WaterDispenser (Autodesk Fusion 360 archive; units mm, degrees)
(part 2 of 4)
sketch "Sketch2" plane through (206.7, 0, 0) normal (1, 0, 0) x axis (0, 0, -1)
  line L1 (-6.7, 180) -> (-1, 180)
  line L2 (-6.7, 170) -> (-6.7, 180)
  line L3 (-1, 170) -> (-6.7, 170)
  line L4 (-1, 160) -> (-1, 170)
  line L5 (-6.7, 160) -> (-1, 160)
  line L6 (-6.7, 150) -> (-6.7, 160)
  line L7 (-1, 150) -> (-6.7, 150)
  line L8 (-1, 140) -> (-1, 150)
  line L9 (-6.7, 140) -> (-1, 140)
  line L10 (-6.7, 130) -> (-6.7, 140)
  line L11 (-1, 130) -> (-6.7, 130)
  line L12 (-1, 120) -> (-1, 130)
  line L13 (-6.7, 120) -> (-1, 120)
  line L14 (-6.7, 110) -> (-6.7, 120)
  line L15 (-1, 110) -> (-6.7, 110)
  line L16 (-1, 100) -> (-1, 110)
  line L17 (-6.7, 100) -> (-1, 100)
  line L18 (-6.7, 90) -> (-6.7, 100)
  line L19 (-1, 90) -> (-6.7, 90)
  line L20 (-1, 80) -> (-1, 90)
  line L21 (-6.7, 80) -> (-1, 80)
  line L22 (-6.7, 70) -> (-6.7, 80)
  line L23 (-1, 70) -> (-6.7, 70)
  line L24 (-1, 60) -> (-1, 70)
  line L25 (-6.7, 60) -> (-1, 60)
  line L26 (-6.7, 50) -> (-6.7, 60)
  line L27 (-1, 50) -> (-6.7, 50)
  line L28 (-1, 40) -> (-1, 50)
  line L29 (-6.7, 40) -> (-1, 40)
  line L30 (-6.7, 30) -> (-6.7, 40)
  line L31 (-1, 30) -> (-6.7, 30)
  line L32 (-1, 20) -> (-1, 30)
  line L33 (-6.7, 20) -> (-1, 20)
  line L34 (-6.7, 10) -> (-6.7, 20)
  line L35 (-1, 10) -> (-6.7, 10)
  line L36 (-1, -5.7) -> (-1, 10)
  line L37 (75, -5.7) -> (-1, -5.7)
  line L38 (75, 245) -> (75, -5.7)
  line L39 (-6.7, 245) -> (75, 245)
  line L40 (-6.7, 230) -> (-6.7, 245)
  line L41 (-1, 230) -> (-6.7, 230)
  line L42 (-1, 220) -> (-1, 230)
  line L43 (-6.7, 220) -> (-1, 220)
  line L44 (-6.7, 210) -> (-6.7, 220)
  line L45 (-1, 210) -> (-6.7, 210)
  line L46 (-1, 200) -> (-1, 210)
  line L47 (-6.7, 200) -> (-1, 200)
  line L48 (-6.7, 190) -> (-6.7, 200)
  line L49 (-1, 190) -> (-6.7, 190)
  line L50 (-1, 180) -> (-1, 190)
  line L51 (-1, 245) -> (-1, 230)
  line L52 (9, 245) -> (-1, 245)
  line L53 (9, 239.3) -> (9, 245)
  line L54 (-1, 239.3) -> (9, 239.3)
  line L55 (-1, 245) -> (-1, 239.3)
  line L56 (9, 239.3) -> (19, 239.3)
  line L57 (9, 245) -> (9, 239.3)
  line L58 (19, 245) -> (9, 245)
  line L59 (19, 239.3) -> (19, 245)
  line L60 (19, 239.3) -> (29, 239.3)
  line L61 (19, 245) -> (19, 239.3)
  line L62 (29, 245) -> (19, 245)
  line L63 (29, 239.3) -> (29, 245)
  line L64 (29, 239.3) -> (39, 239.3)
  line L65 (29, 245) -> (29, 239.3)
  line L66 (39, 245) -> (29, 245)
  line L67 (39, 239.3) -> (39, 245)
  line L68 (39, 239.3) -> (49, 239.3)
  line L69 (39, 245) -> (39, 239.3)
  line L70 (49, 245) -> (39, 245)
  line L71 (49, 239.3) -> (49, 245)
  line L72 (49, 239.3) -> (59, 239.3)
  line L73 (49, 245) -> (49, 239.3)
  line L74 (59, 245) -> (49, 245)
  line L75 (59, 239.3) -> (59, 245)
  line L76 (59, 239.3) -> (69, 239.3)
  line L77 (59, 245) -> (59, 239.3)
  line L78 (69, 245) -> (59, 245)
  line L79 (69, 239.3) -> (69, 245)
  line L80 (75, 239.3) -> (69, 239.3)
  line L81 (75, 245) -> (69, 245)
  line L82 (75, 239.3) -> (75, 245)
  line L83 (9, -5.7) -> (-1, -5.7)
  line L84 (9, 0) -> (9, -5.7)
  line L85 (-1, 0) -> (9, 0)
  line L86 (-1, -5.7) -> (-1, 0)
  line L87 (19, 0) -> (19, -5.7)
  line L88 (9, 0) -> (19, 0)
  line L89 (9, -5.7) -> (9, 0)
  line L90 (19, -5.7) -> (9, -5.7)
  line L91 (29, 0) -> (29, -5.7)
  line L92 (19, 0) -> (29, 0)
  line L93 (19, -5.7) -> (19, 0)
  line L94 (29, -5.7) -> (19, -5.7)
  line L95 (39, 0) -> (39, -5.7)
  line L96 (29, 0) -> (39, 0)
  line L97 (29, -5.7) -> (29, 0)
  line L98 (39, -5.7) -> (29, -5.7)
  line L99 (49, 0) -> (49, -5.7)
  line L100 (39, 0) -> (49, 0)
  line L101 (39, -5.7) -> (39, 0)
  line L102 (49, -5.7) -> (39, -5.7)
  line L103 (59, 0) -> (59, -5.7)
  line L104 (49, 0) -> (59, 0)
  line L105 (49, -5.7) -> (49, 0)
  line L106 (59, -5.7) -> (49, -5.7)
  line L107 (69, 0) -> (69, -5.7)
  line L108 (59, 0) -> (69, 0)
  line L109 (59, -5.7) -> (59, 0)
  line L110 (69, -5.7) -> (59, -5.7)
  line L111 (75, 0) -> (69, 0)
  line L112 (75, -5.7) -> (75, 0)
  line L113 (69, -5.7) -> (75, -5.7)
  point P43 (-1, 230)
  point P52 (-1, 230)
  point P53 (-1, 245)
  point P81 (75, 239.3)
  point P40 (75, 245)
  point P82 (75, 245)
  point P38 (-1, -5.7)
  point P83 (-1, -5.7)
  point P111 (75, 0)
  point P39 (75, -5.7)
  point P112 (75, -5.7)
  point P54 (9, 245)
  point P56 (-1, 239.3)
  point P84 (9, -5.7)
  point P86 (-1, 0)
  coincident P43 P52
  coincident L39 P53
  perpendicular L39 L51
  horizontal L52
  vertical L53
  horizontal L54
  vertical L55
  coincident L38 P81
  perpendicular L38 L80
  coincident P40 P82
  horizontal L83
  vertical L84
  horizontal L85
  vertical L86
  coincident P38 P83
  coincident L38 P111
  perpendicular L38 L111
  coincident P39 P112
  dimension "d241" distance P53 P54 = 10 (= "WoodTooth")
  dimension "d242" distance P53 P56 = 5.7 (= "WoodThickness")
  dimension "d251" distance P83 P84 = 10 (= "WoodTooth")
  dimension "d252" distance P83 P86 = 5.7 (= "WoodThickness")
  dimension "d245" R-Pattern1-uDistance = 10 (= "WoodTooth")
  dimension "d246" R-Pattern1-vDistance = 0
  dimension "d255" R-Pattern2-uDistance = 10 (= "WoodTooth")
  dimension "d256" R-Pattern2-vDistance = 0
extrude "Extrude2" cut sketch "Sketch2" profile of L37 L38 L39 L53 L56 L57 L58 L59 L61 L63 L64 L65 L66 L67 L69 L71 L72 L73 L74 L75 L77 L79 L80 L81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 to an object
work_plane "WorkPlane1" AlongDistance -81.7
mirror "Mirror1" sketch "Sketch1"
sketch "Sketch2" plane through (0, 0, 0) normal (0, -1, 0) x axis (1, 0, 0)
  line L1 (-1, -9) -> (-1, -19)
  line L2 (-6.7, -9) -> (-1, -9)
  line L3 (-6.7, -19) -> (-6.7, -9)
  line L4 (-1, -19) -> (-6.7, -19)
  line L5 (-1, -69) -> (-1, -75)
  line L6 (-6.7, -69) -> (-1, -69)
  line L7 (-6.7, -75) -> (-6.7, -69)
  line L8 (-1, -75) -> (-6.7, -75)
  line L9 (-1, -49) -> (-1, -59)
  line L10 (-6.7, -49) -> (-1, -49)
  line L11 (-6.7, -59) -> (-6.7, -49)
  line L12 (-1, -59) -> (-6.7, -59)
  line L13 (-1, -29) -> (-1, -39)
  line L14 (-6.7, -29) -> (-1, -29)
  line L15 (-6.7, -39) -> (-6.7, -29)
  line L16 (-1, -39) -> (-6.7, -39)
  line L17 (19, 1) -> (9, 1)
  line L18 (19, 6.7) -> (19, 1)
  line L19 (9, 6.7) -> (19, 6.7)
  line L20 (9, 1) -> (9, 6.7)
  line L21 (39, 1) -> (29, 1)
  line L22 (39, 6.7) -> (39, 1)
  line L23 (29, 6.7) -> (39, 6.7)
  line L24 (29, 1) -> (29, 6.7)
  line L25 (59, 1) -> (49, 1)
  line L26 (59, 6.7) -> (59, 1)
  line L27 (49, 6.7) -> (59, 6.7)
  line L28 (49, 1) -> (49, 6.7)
  line L29 (79, 1) -> (69, 1)
  line L30 (79, 6.7) -> (79, 1)
  line L31 (69, 6.7) -> (79, 6.7)
  line L32 (69, 1) -> (69, 6.7)
  line L33 (99, 1) -> (89, 1)
  line L34 (99, 6.7) -> (99, 1)
  line L35 (89, 6.7) -> (99, 6.7)
  line L36 (89, 1) -> (89, 6.7)
  line L37 (119, 1) -> (109, 1)
  line L38 (119, 6.7) -> (119, 1)
  line L39 (109, 6.7) -> (119, 6.7)
  line L40 (109, 1) -> (109, 6.7)
  line L41 (139, 1) -> (129, 1)
  line L42 (139, 6.7) -> (139, 1)
  line L43 (129, 6.7) -> (139, 6.7)
  line L44 (129, 1) -> (129, 6.7)
  line L45 (159, 1) -> (149, 1)
  line L46 (159, 6.7) -> (159, 1)
  line L47 (149, 6.7) -> (159, 6.7)
  line L48 (149, 1) -> (149, 6.7)
  line L49 (179, 1) -> (169, 1)
  line L50 (179, 6.7) -> (179, 1)
  line L51 (169, 6.7) -> (179, 6.7)
  line L52 (169, 1) -> (169, 6.7)
  line L53 (199, 1) -> (189, 1)
  line L54 (199, 6.7) -> (199, 1)
  line L55 (189, 6.7) -> (199, 6.7)
  line L56 (189, 1) -> (189, 6.7)
  line L57 (201, -19) -> (201, -9)
  line L58 (206.7, -19) -> (201, -19)
  line L59 (206.7, -9) -> (206.7, -19)
  line L60 (201, -9) -> (206.7, -9)
  line L61 (201, -39) -> (201, -29)
  line L62 (206.7, -39) -> (201, -39)
  line L63 (206.7, -29) -> (206.7, -39)
  line L64 (201, -29) -> (206.7, -29)
  line L65 (201, -59) -> (201, -49)
  line L66 (206.7, -59) -> (201, -59)
  line L67 (206.7, -49) -> (206.7, -59)
  line L68 (201, -49) -> (206.7, -49)
  line L69 (201, -75) -> (201, -69)
  line L70 (206.7, -75) -> (201, -75)
  line L71 (206.7, -69) -> (206.7, -75)
  line L72 (201, -69) -> (206.7, -69)
  line L73 (206.7, -75) -> (-6.7, -75)
  line L74 (206.7, -69) -> (206.7, -75)
  line L75 (201, -69) -> (206.7, -69)
  line L76 (201, -59) -> (201, -69)
  line L77 (206.7, -59) -> (201, -59)
  line L78 (206.7, -49) -> (206.7, -59)
  line L79 (201, -49) -> (206.7, -49)
  line L80 (201, -39) -> (201, -49)
  line L81 (206.7, -39) -> (201, -39)
  line L82 (206.7, -29) -> (206.7, -39)
  line L83 (201, -29) -> (206.7, -29)
  line L84 (201, -19) -> (201, -29)
  line L85 (206.7, -19) -> (201, -19)
  line L86 (206.7, -9) -> (206.7, -19)
  line L87 (201, -9) -> (206.7, -9)
  line L88 (201, 1) -> (201, -9)
  line L89 (199, 1) -> (201, 1)
  line L90 (199, 6.7) -> (199, 1)
  line L91 (189, 6.7) -> (199, 6.7)
  line L92 (189, 1) -> (189, 6.7)
  line L93 (179, 1) -> (189, 1)
  line L94 (179, 6.7) -> (179, 1)
  line L95 (169, 6.7) -> (179, 6.7)
  line L96 (169, 1) -> (169, 6.7)
  line L97 (159, 1) -> (169, 1)
  line L98 (159, 6.7) -> (159, 1)
  line L99 (149, 6.7) -> (159, 6.7)
  line L100 (149, 1) -> (149, 6.7)
  line L101 (139, 1) -> (149, 1)
  line L102 (139, 6.7) -> (139, 1)
  line L103 (129, 6.7) -> (139, 6.7)
  line L104 (129, 1) -> (129, 6.7)
  line L105 (119, 1) -> (129, 1)
  line L106 (119, 6.7) -> (119, 1)
  line L107 (109, 6.7) -> (119, 6.7)
  line L108 (109, 1) -> (109, 6.7)
  line L109 (99, 1) -> (109, 1)
  line L110 (99, 6.7) -> (99, 1)
  line L111 (89, 6.7) -> (99, 6.7)
  line L112 (89, 1) -> (89, 6.7)
  line L113 (79, 1) -> (89, 1)
  line L114 (79, 6.7) -> (79, 1)
  line L115 (69, 6.7) -> (79, 6.7)
  line L116 (69, 1) -> (69, 6.7)
  line L117 (59, 1) -> (69, 1)
  line L118 (59, 6.7) -> (59, 1)
  line L119 (49, 6.7) -> (59, 6.7)
  line L120 (49, 1) -> (49, 6.7)
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  point P9 (-6.7, -75)
  point P74 (-6.7, -75)
  point P72 (206.7, -75)
  point P75 (206.7, -75)
  point P73 (206.7, -69)
  point P76 (206.7, -69)
  point P70 (201, -69)
  point P77 (201, -69)
  point P78 (201, -69)
  point P67 (201, -59)
  point P79 (201, -59)
  point P80 (201, -59)
  point P68 (206.7, -59)
  point P81 (206.7, -59)
  point P69 (206.7, -49)
  point P82 (206.7, -49)
  point P83 (206.7, -49)
  point P66 (201, -49)
  point P84 (201, -49)
  point P63 (201, -39)
  point P85 (201, -39)
  point P86 (201, -39)
  point P64 (206.7, -39)
  point P87 (206.7, -39)
  point P88 (206.7, -39)
  point P65 (206.7, -29)
  point P89 (206.7, -29)
  point P62 (201, -29)
  point P90 (201, -29)
  point P91 (201, -29)
  point P59 (201, -19)
  point P92 (201, -19)
  point P60 (206.7, -19)
  point P93 (206.7, -19)
  point P61 (206.7, -9)
  point P94 (206.7, -9)
  point P95 (206.7, -9)
  point P58 (201, -9)
  point P96 (201, -9)
  point P55 (199, 1)
  point P98 (199, 1)
  point P56 (199, 6.7)
  point P99 (199, 6.7)
  point P100 (199, 6.7)
  point P57 (189, 6.7)
  point P101 (189, 6.7)
  point P102 (189, 6.7)
  point P54 (189, 1)
  point P103 (189, 1)
  point P104 (189, 1)
  point P51 (179, 1)
  point P105 (179, 1)
  point P52 (179, 6.7)
  point P106 (179, 6.7)
  point P53 (169, 6.7)
  point P107 (169, 6.7)
  point P50 (169, 1)
  point P108 (169, 1)
  point P109 (169, 1)
  point P47 (159, 1)
  point P110 (159, 1)
  point P48 (159, 6.7)
  point P111 (159, 6.7)
  point P112 (159, 6.7)
  point P49 (149, 6.7)
  point P113 (149, 6.7)
  point P46 (149, 1)
  point P114 (149, 1)
  point P43 (139, 1)
  point P115 (139, 1)
  point P44 (139, 6.7)
  point P116 (139, 6.7)
  point P117 (139, 6.7)
  point P45 (129, 6.7)
  point P118 (129, 6.7)
  point P119 (129, 6.7)
  point P42 (129, 1)
  point P120 (129, 1)
  point P39 (119, 1)
  point P121 (119, 1)
  point P40 (119, 6.7)
  point P122 (119, 6.7)
  point P123 (119, 6.7)
  point P41 (109, 6.7)
  point P124 (109, 6.7)
  point P38 (109, 1)
  point P125 (109, 1)
  point P126 (109, 1)
  point P35 (99, 1)
  point P127 (99, 1)
  point P128 (99, 1)
  point P36 (99, 6.7)
  point P129 (99, 6.7)
  point P37 (89, 6.7)
  point P130 (89, 6.7)
  point P34 (89, 1)
  point P131 (89, 1)
  point P132 (89, 1)
  point P31 (79, 1)
  point P133 (79, 1)
  point P134 (79, 1)
  point P32 (79, 6.7)
  point P135 (79, 6.7)
  point P33 (69, 6.7)
  point P136 (69, 6.7)
  point P137 (69, 6.7)
  point P30 (69, 1)
  point P138 (69, 1)
  point P27 (59, 1)
  point P139 (59, 1)
  point P140 (59, 1)
  point P28 (59, 6.7)
  point P141 (59, 6.7)
  point P29 (49, 6.7)
  point P142 (49, 6.7)
  point P143 (49, 6.7)
  point P26 (49, 1)
  point P144 (49, 1)
  point P23 (39, 1)
  point P145 (39, 1)
  point P24 (39, 6.7)
  point P146 (39, 6.7)
  point P147 (39, 6.7)
  point P25 (29, 6.7)
  point P148 (29, 6.7)
  point P22 (29, 1)
  point P149 (29, 1)
  point P19 (19, 1)
  point P150 (19, 1)
  point P20 (19, 6.7)
  point P151 (19, 6.7)
  point P21 (9, 6.7)
  point P152 (9, 6.7)
  point P18 (9, 1)
  point P153 (9, 1)
  point P154 (9, 1)
  point P3 (-1, -9)
  point P156 (-1, -9)
  point P4 (-6.7, -9)
  point P157 (-6.7, -9)
  point P5 (-6.7, -19)
  point P158 (-6.7, -19)
  point P2 (-1, -19)
  point P159 (-1, -19)
  point P15 (-1, -29)
  point P160 (-1, -29)
  point P161 (-1, -29)
  point P16 (-6.7, -29)
  point P162 (-6.7, -29)
  point P17 (-6.7, -39)
  point P163 (-6.7, -39)
  point P14 (-1, -39)
  point P164 (-1, -39)
  point P165 (-1, -39)
  point P11 (-1, -49)
  point P166 (-1, -49)
  point P12 (-6.7, -49)
  point P167 (-6.7, -49)
  point P13 (-6.7, -59)
  point P168 (-6.7, -59)
  point P169 (-6.7, -59)
  point P10 (-1, -59)
  point P170 (-1, -59)
  point P7 (-1, -69)
  point P171 (-1, -69)
  point P172 (-1, -69)
  point P8 (-6.7, -69)
  point P173 (-6.7, -69)
  point P174 (-6.7, -75)
  coincident P9 P74
  coincident P72 P75
  coincident P73 P76
  coincident P70 P77
  coincident P70 P78
  coincident P67 P79
  coincident P67 P80
  coincident P68 P81
  coincident P69 P82
  coincident P69 P83
  coincident P66 P84
  coincident P63 P85
  coincident P63 P86
  coincident P64 P87
  coincident P64 P88
  coincident P65 P89
  coincident P62 P90
  coincident P62 P91
  coincident P59 P92
  coincident P60 P93
  coincident P61 P94
  coincident P61 P95
  coincident P58 P96
  perpendicular L53 L88
  coincident P55 P98
  perpendicular L54 L89
  coincident P56 P99
  coincident P56 P100
  coincident P57 P101
  coincident P57 P102
  coincident P54 P103
  coincident P54 P104
  coincident P51 P105
  coincident P52 P106
  coincident P53 P107
  coincident P50 P108
  coincident P50 P109
  coincident P47 P110
  coincident P48 P111
  coincident P48 P112
  coincident P49 P113
  coincident P46 P114
  coincident P43 P115
  coincident P44 P116
  coincident P44 P117
  coincident P45 P118
  coincident P45 P119
  coincident P42 P120
  coincident P39 P121
  coincident P40 P122
  coincident P40 P123
  coincident P41 P124
  coincident P38 P125
  coincident P38 P126
  coincident P35 P127
  coincident P35 P128
  coincident P36 P129
  coincident P37 P130
  coincident P34 P131
  coincident P34 P132
  coincident P31 P133
  coincident P31 P134
  coincident P32 P135
  coincident P33 P136
  coincident P33 P137
  coincident P30 P138
  coincident P27 P139
  coincident P27 P140
  coincident P28 P141
  coincident P29 P142
  coincident P29 P143
  coincident P26 P144
  coincident P23 P145
  coincident P24 P146
  coincident P24 P147
  coincident P25 P148
  coincident P22 P149
  coincident P19 P150
  coincident P20 P151
  coincident P21 P152
  coincident P18 P153
  coincident P18 P154
  coincident P3 P156
  coincident P4 P157
  coincident P5 P158
  coincident P2 P159
  coincident P15 P160
  coincident P15 P161
  coincident P16 P162
  coincident P17 P163
  coincident P14 P164
  coincident P14 P165
  coincident P11 P166
  coincident P12 P167
  coincident P13 P168
  coincident P13 P169
  coincident P10 P170
  coincident P7 P171
  coincident P7 P172
  coincident P8 P173
  coincident P9 P174
extrude "Extrude1" new body sketch "Sketch2" along normal blind 5.7 (= "WoodThickness")
work_plane "WorkPlane1" AlongDistance -81.7
mirror "Mirror1"
copy_paste "CutPaste3"
sketch "Sketch1" plane through (0, 239.3, 0) normal (0, 1, 0) x axis (-1, 0, 0)
  line L1 (-105.7, -121) -> (-105.7, -111)
  line L2 (-100, -121) -> (-105.7, -121)
  line L3 (-100, -111) -> (-100, -121)
  line L4 (-105.7, -111) -> (-100, -111)
  line L5 (-105.7, -75) -> (-105.7, -69)
  line L6 (-100, -75) -> (-105.7, -75)
  line L7 (-100, -69) -> (-100, -75)
  line L8 (-105.7, -69) -> (-100, -69)
  line L9 (-105.7, -59) -> (-105.7, -49)
  line L10 (-100, -59) -> (-105.7, -59)
  line L11 (-100, -49) -> (-100, -59)
  line L12 (-105.7, -49) -> (-100, -49)
  line L13 (-105.7, -39) -> (-105.7, -29)
  line L14 (-100, -39) -> (-105.7, -39)
  line L15 (-100, -29) -> (-100, -39)
  line L16 (-105.7, -29) -> (-100, -29)
  line L17 (-105.7, -19) -> (-105.7, -9)
  line L18 (-100, -19) -> (-105.7, -19)
  line L19 (-100, -9) -> (-100, -19)
  line L20 (-105.7, -9) -> (-100, -9)
  line L21 (-121, 1) -> (-131, 1)
  line L22 (-121, 6.7) -> (-121, 1)
  line L23 (-131, 6.7) -> (-121, 6.7)
  line L24 (-131, 1) -> (-131, 6.7)
  line L25 (-141, 1) -> (-151, 1)
  line L26 (-141, 6.7) -> (-141, 1)
  line L27 (-151, 6.7) -> (-141, 6.7)
  line L28 (-151, 1) -> (-151, 6.7)
  line L29 (-161, 1) -> (-171, 1)
  line L30 (-161, 6.7) -> (-161, 1)
  line L31 (-171, 6.7) -> (-161, 6.7)
  line L32 (-171, 1) -> (-171, 6.7)
  line L33 (-181, 1) -> (-191, 1)
  line L34 (-181, 6.7) -> (-181, 1)
  line L35 (-191, 6.7) -> (-181, 6.7)
  line L36 (-191, 1) -> (-191, 6.7)
  line L37 (-201, -9) -> (-201, -19)
  line L38 (-206.7, -9) -> (-201, -9)
  line L39 (-206.7, -19) -> (-206.7, -9)
  line L40 (-201, -19) -> (-206.7, -19)
  line L41 (-201, -29) -> (-201, -39)
  line L42 (-206.7, -29) -> (-201, -29)
  line L43 (-206.7, -39) -> (-206.7, -29)
  line L44 (-201, -39) -> (-206.7, -39)
  line L45 (-201, -49) -> (-201, -59)
  line L46 (-206.7, -49) -> (-201, -49)
  line L47 (-206.7, -59) -> (-206.7, -49)
  line L48 (-201, -59) -> (-206.7, -59)
  line L49 (-201, -69) -> (-201, -75)
  line L50 (-206.7, -69) -> (-201, -69)
  line L51 (-206.7, -75) -> (-206.7, -69)
  line L52 (-201, -75) -> (-206.7, -75)
  line L53 (-100, -75) -> (-206.7, -75)
  line L54 (-100, -69) -> (-100, -75)
  line L55 (-105.7, -69) -> (-100, -69)
  line L56 (-105.7, -59) -> (-105.7, -69)
  line L57 (-100, -59) -> (-105.7, -59)
  line L58 (-100, -49) -> (-100, -59)
  line L59 (-105.7, -49) -> (-100, -49)
  line L60 (-105.7, -39) -> (-105.7, -49)
  line L61 (-100, -39) -> (-105.7, -39)
  line L62 (-100, -29) -> (-100, -39)
  line L63 (-100, -29) -> (-105.7, -29)
  line L64 (-105.7, -19) -> (-105.7, -29)
  line L65 (-100, -19) -> (-105.7, -19)
  line L66 (-100, -9) -> (-100, -19)
  line L67 (-105.7, -9) -> (-100, -9)
  line L68 (-105.7, 6.7) -> (-105.7, -9)
  line L69 (-121, 6.7) -> (-105.7, 6.7)
  line L70 (-121, 1) -> (-121, 6.7)
  line L71 (-131, 1) -> (-121, 1)
  line L72 (-131, 6.7) -> (-131, 1)
  line L73 (-141, 6.7) -> (-131, 6.7)
  line L74 (-141, 1) -> (-141, 6.7)
  line L75 (-151, 1) -> (-141, 1)
  line L76 (-151, 6.7) -> (-151, 1)
  line L77 (-161, 6.7) -> (-151, 6.7)
  line L78 (-161, 1) -> (-161, 6.7)
  line L79 (-171, 6.7) -> (-161, 6.7)
  line L80 (-171, 1) -> (-171, 6.7)
  line L81 (-181, 1) -> (-171, 1)
  line L82 (-181, 6.7) -> (-181, 1)
  line L83 (-191, 6.7) -> (-181, 6.7)
  line L84 (-191, 1) -> (-191, 6.7)
  line L85 (-141, 6.7) -> (-151, 6.7)
  line L86 (-121, 6.7) -> (-131, 6.7)
  line L87 (-201, 1) -> (-191, 1)
  line L88 (-201, -9) -> (-201, 1)
  line L89 (-201, -9) -> (-206.7, -9)
  line L90 (-206.7, -19) -> (-206.7, -9)
  line L91 (-201, -19) -> (-206.7, -19)
  line L92 (-201, -29) -> (-201, -19)
  line L93 (-206.7, -29) -> (-201, -29)
  line L94 (-206.7, -39) -> (-206.7, -29)
  line L95 (-201, -39) -> (-206.7, -39)
  line L96 (-201, -49) -> (-201, -39)
  line L97 (-206.7, -49) -> (-201, -49)
  line L98 (-206.7, -59) -> (-206.7, -49)
  line L99 (-201, -59) -> (-206.7, -59)
  line L100 (-201, -69) -> (-201, -59)
  line L101 (-206.7, -69) -> (-201, -69)
  line L102 (-206.7, -75) -> (-206.7, -69)
  line L103 (-105.7, 1) -> (-121, 1)
  line L104 (-141, 1) -> (-131, 1)
  line L105 (-161, 1) -> (-151, 1)
  point P53 (-206.7, -75)
  point P54 (-206.7, -75)
  point P8 (-100, -75)
  point P55 (-100, -75)
  point P9 (-100, -69)
  point P56 (-100, -69)
  point P6 (-105.7, -69)
  point P57 (-105.7, -69)
  point P11 (-105.7, -59)
  point P58 (-105.7, -59)
  point P59 (-105.7, -59)
  point P12 (-100, -59)
  point P60 (-100, -59)
  point P61 (-100, -59)
  point P13 (-100, -49)
  point P62 (-100, -49)
  point P63 (-100, -49)
  point P10 (-105.7, -49)
  point P64 (-105.7, -49)
  point P65 (-105.7, -49)
  point P15 (-105.7, -39)
  point P66 (-105.7, -39)
  point P67 (-105.7, -39)
  point P16 (-100, -39)
  point P68 (-100, -39)
  point P69 (-100, -39)
  point P17 (-100, -29)
  point P70 (-100, -29)
  point P14 (-105.7, -29)
  point P71 (-105.7, -29)
  point P72 (-105.7, -29)
  point P19 (-105.7, -19)
  point P73 (-105.7, -19)
  point P74 (-105.7, -19)
  point P20 (-100, -19)
  point P75 (-100, -19)
  point P21 (-100, -9)
  point P76 (-100, -9)
  point P18 (-105.7, -9)
  point P77 (-105.7, -9)
  point P23 (-121, 1)
  point P80 (-121, 1)
  point P81 (-121, 1)
  point P22 (-131, 1)
  point P82 (-131, 1)
  point P25 (-131, 6.7)
  point P83 (-131, 6.7)
  point P28 (-141, 6.7)
  point P84 (-141, 6.7)
  point P85 (-141, 6.7)
  point P27 (-141, 1)
  point P86 (-141, 1)
  point P87 (-141, 1)
  point P26 (-151, 1)
  point P88 (-151, 1)
  point P29 (-151, 6.7)
  point P89 (-151, 6.7)
  point P32 (-161, 6.7)
  point P90 (-161, 6.7)
  point P91 (-161, 6.7)
  point P31 (-161, 1)
  point P92 (-161, 1)
  point P33 (-171, 6.7)
  point P93 (-171, 6.7)
  point P30 (-171, 1)
  point P94 (-171, 1)
  point P95 (-171, 1)
  point P35 (-181, 1)
  point P96 (-181, 1)
  point P36 (-181, 6.7)
  point P97 (-181, 6.7)
  point P37 (-191, 6.7)
  point P98 (-191, 6.7)
  point P34 (-191, 1)
  point P99 (-191, 1)
  point P100 (-151, 6.7)
  point P101 (-131, 6.7)
  point P24 (-121, 6.7)
  point P102 (-121, 6.7)
  point P103 (-191, 1)
  point P39 (-201, -9)
  point P105 (-201, -9)
  point P40 (-206.7, -9)
  point P106 (-206.7, -9)
  point P107 (-206.7, -9)
  point P41 (-206.7, -19)
  point P108 (-206.7, -19)
  point P38 (-201, -19)
  point P109 (-201, -19)
  point P43 (-201, -29)
  point P110 (-201, -29)
  point P111 (-201, -29)
  point P44 (-206.7, -29)
  point P112 (-206.7, -29)
  point P45 (-206.7, -39)
  point P113 (-206.7, -39)
  point P42 (-201, -39)
  point P114 (-201, -39)
  point P47 (-201, -49)
  point P115 (-201, -49)
  point P48 (-206.7, -49)
  point P116 (-206.7, -49)
  point P117 (-206.7, -49)
  point P49 (-206.7, -59)
  point P118 (-206.7, -59)
  point P46 (-201, -59)
  point P119 (-201, -59)
  point P120 (-201, -59)
  point P51 (-201, -69)
  point P121 (-201, -69)
  point P52 (-206.7, -69)
  point P122 (-206.7, -69)
  point P123 (-206.7, -75)
  point P124 (-105.7, 1)
  point P125 (-131, 1)
  point P126 (-151, 1)
  point P127 (-161, 1)
  coincident P53 P54
  coincident P8 P55
  coincident P9 P56
  coincident P6 P57
  coincident P11 P58
  coincident P11 P59
  coincident P12 P60
  coincident P12 P61
  coincident P13 P62
  coincident P13 P63
  coincident P10 P64
  coincident P10 P65
  coincident P15 P66
  coincident P15 P67
  coincident P16 P68
  coincident P16 P69
  coincident P17 P70
  coincident P14 P71
  coincident P14 P72
  coincident P19 P73
  coincident P19 P74
  coincident P20 P75
  coincident P21 P76
  coincident P18 P77
  perpendicular L23 L68
  perpendicular L68 L69
  coincident P23 P80
  perpendicular L21 L70
  coincident P23 P81
  coincident P22 P82
  coincident P25 P83
  coincident P28 P84
  coincident P28 P85
  coincident P27 P86
  coincident P27 P87
  coincident P26 P88
  coincident P29 P89
  coincident P32 P90
  coincident P32 P91
  coincident P31 P92
  coincident P33 P93
  coincident P30 P94
  coincident P30 P95
  coincident P35 P96
  coincident P36 P97
  coincident P37 P98
  coincident P34 P99
  coincident P29 P100
  coincident P25 P101
  coincident P24 P102
  coincident P34 P103
  perpendicular L37 L87
  coincident P39 P105
  perpendicular L38 L88
  coincident P40 P106
  coincident P40 P107
  coincident P41 P108
  coincident P38 P109
  coincident P43 P110
  coincident P43 P111
  coincident P44 P112
  coincident P45 P113
  coincident P42 P114
  coincident P47 P115
  coincident P48 P116
  coincident P48 P117
  coincident P49 P118
  coincident P46 P119
  coincident P46 P120
  coincident P51 P121
  coincident P52 P122
  coincident P53 P123
  coincident L68 P124
  perpendicular L68 L103
  coincident P22 P125
  coincident P26 P126
  coincident P31 P127
extrude "Extrude1" new body sketch "Sketch1" profile of L5 L6 L7 L8 L9 L10 L11 L12 L13 L14 L15 L16 L17 L18 L19 L20 L21 L22 L23 L24 L25 L26 L27 L28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 along normal blind 5.7 (= "WoodThickness")
work_plane "WorkPlane1" AlongDistance -81.7
mirror "Mirror1"
work_plane "WorkPlane1" AlongDistance 120 (= "WaterFallHeight")
sketch "Sketch5" plane through (100, 205, -75) normal (0, 1, 0) x axis (1, 0, 0)
sketch "Sketch1" plane through (0, 85, 0) normal (0, 1, 0) x axis (-1, 0, 0)
  line L1 (-100, -151) -> (6.7, -151)
  line L2 (-100, -156.7) -> (-100, -151)
  line L3 (6.7, -156.7) -> (-100, -156.7)
  line L4 (6.7, -151) -> (6.7, -156.7)
work_plane "WorkPlane1" sketch "Sketch1" AlongDistance 120 (= "WaterFallHeight")
sketch "Sketch2" plane through (46.65, 205, -153.85) normal (0, 1, 0) x axis (1, 0, 0)
  line L1 (153.35, -24.75) -> (153.35, -153.85)
  line L2 (153.35, -153.85) -> (-46.65, -153.85)
  line L3 (-46.65, -3.85) -> (113.519, -3.85)
  line L4 (59.05, -52.85) -> (59.05, -62.85)
  line L5 (153.35, -153.85) -> (153.35, -3.85)
  line L6 (60.05, -153.85) -> (153.35, -153.85)
  line L7 (60.05, -3.85) -> (60.05, -153.85)
  line L8 (153.35, -3.85) -> (60.05, -3.85)
  circle C1 centre (140.4, -16.8) radius 4.95
  point P2 (153.35, -153.85)
  point P11 (153.35, -153.85)
  point P12 (60.05, -153.85)
  point P13 (60.05, -3.85)
  coincident P2 P11
  perpendicular L2 L5
  coincident L2 P12
  perpendicular L1 L6
  coincident L3 P13
  perpendicular L3 L7
  perpendicular L5 L8
  dimension "d267" distance L4 L7 = 1 (= "GapBetweenWaterContainer")
extrude "Extrude1" new body sketch "Sketch2" profile of L1 L2 L3 C1 L5 L6 L7 L8 along normal blind 5 (= "WaterContainerBorderThickness")
sketch "Sketch4" plane through (0, 210, 0) normal (0, 1, 0) x axis (-1, 0, 0)
  line L1 (-106.7, 0) -> (-106.7, -150)
  line L2 (-200, 0) -> (-106.7, 0)
  line L3 (-200, -150) -> (-200, 0)
  line L4 (-106.7, -150) -> (-200, -150)
  line L5 (-195, -145) -> (-195, -5)
  line L6 (-111.7, -145) -> (-195, -145)
  line L7 (-111.7, -5) -> (-111.7, -145)
  line L8 (-195, -5) -> (-111.7, -5)
  circle C1 centre (-187.05, -137.05) radius 4.95
extrude "Extrude2" add sketch "Sketch4" profile of L1 L2 L3 L4 L5 L6 L7 L8 to an object offset 1 (= "GapBetweenWaterContainer")
sketch "Sketch5" plane through (0, 210, 0) normal (0, 1, 0) x axis (-1, 0, 0)
  line L1 (-195, -5) -> (-111.7, -5)
  line L2 (-195, -145) -> (-195, -5)
  line L3 (-111.7, -145) -> (-195, -145)
  line L4 (-111.7, -5) -> (-111.7, -145)
  circle C1 centre (-187.05, -137.05) radius 4.95
  circle C2 centre (-187.05, -137.05) radius 9.95
  dimension "d273" = 5 (= "WaterContainerBorderThickness")
work_plane "WorkPlane2" AlongDistance 7.95
sketch "Sketch6" plane through (187.05, 224.15, -75) normal (-1, 0, 0) x axis (0, 0, -1)
  line L1 (57.1, 14.15) -> (67, 14.15)
  line L2 (57.1, 19.15) -> (67, 19.15)
  line L3 (-75, 19.15) -> (75, 19.15)
  line L4 (72, 14.15) -> (52.1, 14.15)
  line L5 (-70, -14.15) -> (70, -14.15)
  line L6 (9, -11.15) -> (70, -11.15)
  line L7 (21, -6.4) -> (70, -6.4)
  line L8 (-2.95, 17) -> (-2.95, -19)
  line L9 (-2.95, 14.15) -> (62.05, 14.15)
  line L10 (29.55, -25) -> (29.55, 14.15)
  line L11 (-2.95, -14.15) -> (10.626, -2.3285)
  closed curve K1 centre (29.55, 14.15)
  closed curve K2 centre (29.55, 14.15)
  point P19 (-2.95, 14.15)
  point P20 (29.55, 14.15)
  point P22 (29.55, 14.15)
  point P23 (-1.9456, 19.15)
  point P24 (-2.95, -14.15)
  point P25 (10.626, -2.3285)
  point P18 (62.05, 14.15)
  parallel L5 L6
  horizontal L7
  perpendicular L5 L8
  coincident L8 P19
  perpendicular L8 L9
  midpoint L9 P20
  perpendicular L5 L10
  coincident P20 P22
  coincident L3 P23
  coincident L5 P24
  coincident L8 P24
  coincident P25 K1
  concentric K1 K2
  dimension "d275" distance L5 L6 = 3
  dimension "d276" distance L6 L7 = 4.75 (= "LatexTubeDiameter / 2")
  dimension "d277" distance L8 P18 = 65
sweep "Sweep1" sketch "Sketch5" TwistAngle 0 TaperAngle 0
sketch "Sketch7" plane through (111.7, 0, 0) normal (1, 0, 0) x axis (0, 0, -1)
  line L1 (5, 238.3) -> (145, 238.3)
  line L2 (5, 210) -> (5, 238.3)
  line L3 (145, 210) -> (5, 210)
  line L4 (145, 238.3) -> (145, 210)
  line L5 (75, 210) -> (75, 238.3)
  circle C1 centre (75, 212.5) radius 3
  point P6 (75, 238.3)
  point P7 (75, 210)
  point P8 (75, 212.5)
  midpoint L1 P6
  midpoint L3 P7
  coincident L5 P8
  dimension "d285" diameter C1 = 6 (= "WaterFallDiameter")
  dimension "d286" distance L3 P8 = 2.5 (= "( WaterFallDiameter / 2 ) - 0.5 mm")
extrude "Extrude3" cut sketch "Sketch7" profile of L3 C1 blind 10 Side2Offset 0
fillet "Fillet1" radius 2
work_plane "WorkPlane3" AlongDistance -75
sketch "Sketch8" plane through (153.35, 221.65, -75) normal (0, 0, 1) x axis (1, 0, 0)
  line L1 (46.65, -16.65) -> (-46.65, -16.65)
  line L2 (46.65, 16.65) -> (46.65, -16.65)
  line L3 (-46.65, 16.65) -> (46.65, 16.65)
  line L4 (-46.65, -16.65) -> (-46.65, 16.65)
  line L5 (-46.65, -16.65) -> (46.65, -16.65)
  line L6 (-46.65, 16.65) -> (-46.65, -16.65)
  line L7 (-46.65, -6.15) -> (-46.65, -12.15)
  line L8 (-46.65, -9.15) -> (-41.65, -9.15)
  line L9 (-153.35, -16.65) -> (6.819, -16.65)
  line L10 (-46.65, -16.65) -> (-153.35, -16.65)
  line L11 (-100, 5) -> (-100, -16.65)
  line L12 (-70, -13.65) -> (-133.26, -13.65)
  line L13 (-46.65, -9.15) -> (-100, -13.65)
  point P10 (-41.65, -9.15)
  point P13 (-41.65, -9.15)
  point P14 (-46.65, -9.15)
  point P16 (-153.35, -16.65)
  point P17 (-153.35, -16.65)
  point P2 (-46.65, -16.65)
  point P18 (-46.65, -16.65)
  point P19 (-100, -16.65)
  point P23 (-100, -13.65)
  coincident P10 P13
  midpoint L7 P14
  coincident P16 P17
  coincident P2 P18
  midpoint L10 P19
  perpendicular L10 L11
  parallel L10 L12
  coincident L12 P23
  coincident L11 P23
  dimension "d310" distance L10 L12 = 3
sketch "Sketch9" plane through (106.7, 0, 0) normal (-1, 0, 0) x axis (0, 0, 1)
  line L1 (0, 205) -> (-150, 205)
  line L2 (0, 238.3) -> (0, 205)
  line L3 (-150, 238.3) -> (0, 238.3)
  line L4 (-150, 205) -> (-150, 238.3)
  line L5 (-80.6382, 214.5521) -> (-75, 212.5)
  line L6 (-69, 212.5) -> (-75, 212.5)
  line L7 (-69.3618, 214.5521) -> (-75, 212.5)
  line L8 (-69, 212.5) -> (-75, 212.5)
  circle C1 centre (-75, 212.5) radius 3
  circle C2 centre (-75, 212.5) radius 3
  circle C3 centre (-75, 212.5) radius 6
  point P7 (-75, 212.5)
  point P9 (-75, 212.5)
  point P12 (-75, 212.5)
  horizontal L6
  coincident P7 P9
  horizontal L8
  coincident P7 P12
  dimension "d293" distance C1 = 3 (= "WaterContainerHoleThickness")
  dimension "d308" angle L5 L6 = 160
  dimension "d309" angle L7 L8 = 20
sketch "Sketch10" plane through (0, 0, -75) normal (0, 0, 1) x axis (1, 0, 0)
sketch "Sketch11" plane through (153.35, 205, -75) normal (0, 1, 0) x axis (1, 0, 0)
sketch "Sketch12" plane through (46.65, 205, -153.85) normal (0, 1, 0) x axis (1, 0, 0)
  line L1 (0, -160) -> (160, -160)
  line L2 (0, 30) -> (0, -160)
  line L3 (160, 30) -> (0, 30)
  line L4 (160, -160) -> (160, 30)
  horizontal L1
  vertical L2
  horizontal L3
  vertical L4
extrude "Extrude4" cut sketch "Sketch12" against normal blind 20
sweep "Sweep3" sketch "Sketch9" TwistAngle 0 TaperAngle 0
sketch "Sketch13" plane through (53.35, 0, 0) normal (-1, 0, 0) x axis (0, 0, 1)
  line L1 (-80.6382, 210.0521) -> (-77.8191, 209.0261)
  line L2 (-72.1809, 209.0261) -> (-69.3618, 210.0521)
  line L3 (-78, 202.8038) -> (-78, 208)
  line L4 (-72, 202.8038) -> (-72, 208)
  arc A1 centre (-75, 208) radius 6 clockwise from (-69.3618, 210.0521) to (-80.6382, 210.0521)
  arc A2 centre (-75, 208) radius 3 clockwise from (-72.1809, 209.0261) to (-77.8191, 209.0261)
  point P8 (-78, 202.8038)
  point P7 (-78, 208)
  point P9 (-72, 208)
  point P10 (-72, 202.8038)
  coincident A1 P8
  vertical L3
  tangent A2 L3
  coincident A2 P7
  vertical L4
  tangent A2 L4
  coincident A2 P9
  coincident A1 P10
extrude "Extrude5" add sketch "Sketch13" along normal blind 10 (= "WaterFallStopperDistance")
sketch "Sketch14" plane through (43.35, 0, 0) normal (-1, 0, 0) x axis (0, 0, 1)
  line L1 (-72, 202.8038) -> (-72, 208)
  line L2 (-72.1809, 209.0261) -> (-69.3618, 210.0521)
  line L3 (-80.6382, 210.0521) -> (-77.8191, 209.0261)
  line L4 (-78, 208) -> (-78, 202.8038)
  line L5 (-72, 208) -> (-72, 202.8038)
  line L6 (-78, 202.8038) -> (-78, 208)
  line L7 (-72.1809, 209.0261) -> (-77.8191, 209.0261)
  arc A1 centre (-75, 208) radius 6 clockwise from (-69.3618, 210.0521) to (-72, 202.8038)
  arc A2 centre (-75, 208) radius 3 clockwise from (-72.1809, 209.0261) to (-72, 208)
  arc A3 centre (-75, 208) radius 6 clockwise from (-78, 202.8038) to (-80.6382, 210.0521)
  arc A4 centre (-75, 208) radius 3 clockwise from (-78, 208) to (-77.8191, 209.0261)
  arc A5 centre (-75, 208) radius 3 clockwise from (-72, 208) to (-78, 208)
  arc A6 centre (-75, 208) radius 6 clockwise from (-72, 202.8038) to (-78, 202.8038)
  point P7 (-77.8191, 209.0261)
  point P17 (-77.8191, 209.0261)
  point P6 (-72.1809, 209.0261)
  point P18 (-72.1809, 209.0261)
  coincident P7 P17
  coincident P6 P18
extrude "Extrude6" add sketch "Sketch14" along normal blind 3 (= "WaterContainerHoleThickness")
combine "Combine1"
fillet "Fillet2" radius 4
fillet "Fillet3" radius 3
fillet "Fillet4" radius 1
fillet "Fillet5" radius 3
fillet "Fillet6" radius 5
fillet "Fillet7" radius 5
fillet "Fillet8" radius 1
fillet "Fillet9" radius 1
fillet "Fillet10" radius 0.5
fillet "Fillet11" radius 2
fillet "Fillet12" radius 1
fillet "Fillet13" radius 2
fillet "Fillet14" radius 2
copy_paste "CutPaste4"
sketch "Sketch1" plane through (46.65, 205, -153.85) normal (0, 1, 0) x axis (1, 0, 0)
sketch "Sketch4" plane through (100, 0, 0) normal (-1, 0, 0) x axis (0, 0, 1)
  line L1 (-39, 245) -> (-39, 239.3)
  line L2 (-49, 245) -> (-39, 245)
  line L3 (-49, 239.3) -> (-49, 245)
  line L4 (-59, 239.3) -> (-49, 239.3)
  line L5 (-59, 245) -> (-59, 239.3)
  line L6 (-69, 245) -> (-59, 245)
  line L7 (-69, 239.3) -> (-69, 245)
  line L8 (-75, 239.3) -> (-69, 239.3)
  line L9 (-75, 85) -> (-75, 239.3)
  line L10 (1, 85) -> (-75, 85)
  line L11 (1, 99.3) -> (1, 85)
  line L12 (6.7, 99.3) -> (1, 99.3)
  line L13 (6.7, 109.3) -> (6.7, 99.3)
  line L14 (1, 109.3) -> (6.7, 109.3)
  line L15 (1, 119.3) -> (1, 109.3)
  line L16 (6.7, 119.3) -> (1, 119.3)
  line L17 (6.7, 129.3) -> (6.7, 119.3)
  line L18 (1, 129.3) -> (6.7, 129.3)
  line L19 (1, 139.3) -> (1, 129.3)
  line L20 (6.7, 139.3) -> (1, 139.3)
  line L21 (6.7, 149.3) -> (6.7, 139.3)
  line L22 (1, 149.3) -> (6.7, 149.3)
  line L23 (1, 159.3) -> (1, 149.3)
  line L24 (6.7, 159.3) -> (1, 159.3)
  line L25 (6.7, 169.3) -> (6.7, 159.3)
  line L26 (1, 169.3) -> (6.7, 169.3)
  line L27 (1, 179.3) -> (1, 169.3)
  line L28 (6.7, 179.3) -> (1, 179.3)
  line L29 (6.7, 189.3) -> (6.7, 179.3)
  line L30 (1, 189.3) -> (6.7, 189.3)
  line L31 (1, 199.3) -> (1, 189.3)
  line L32 (6.7, 199.3) -> (1, 199.3)
  line L33 (6.7, 209.3) -> (6.7, 199.3)
  line L34 (1, 209.3) -> (6.7, 209.3)
  line L35 (1, 219.3) -> (1, 209.3)
  line L36 (6.7, 219.3) -> (1, 219.3)
  line L37 (6.7, 229.3) -> (6.7, 219.3)
  line L38 (1, 229.3) -> (6.7, 229.3)
  line L39 (1, 245) -> (1, 229.3)
  line L40 (-9, 245) -> (1, 245)
  line L41 (-9, 239.3) -> (-9, 245)
  line L42 (-19, 239.3) -> (-9, 239.3)
  line L43 (-19, 245) -> (-19, 239.3)
  line L44 (-29, 245) -> (-19, 245)
  line L45 (-29, 239.3) -> (-29, 245)
  line L46 (-39, 239.3) -> (-29, 239.3)
  curve K1 (-70.475, 204.1489) -> (-72, 202.8943)
  curve K2 (-72, 202.8943) -> (-78, 202.8943)
  curve K3 (-79.525, 204.1489) -> (-79.8, 204.4)
  line L47 (-80.9351, 212.9639) -> (-80.9351, 208.8804)
  curve K4 (-80.9351, 212.9639) -> (-69.0649, 212.9639)
  line L48 (-69.0649, 208.8804) -> (-69.0649, 212.9639)
  curve K5 (-70.2, 204.4) -> (-70.475, 204.1489)
  line L49 (-67.7291, 214.3397) -> (-82.2709, 214.3397)
  curve K6 (-78, 202.8943) -> (-79.525, 204.1489)
  arc A1 centre (-75, 208) radius 6 clockwise from (-79.8, 204.4) to (-81, 208)
  arc A2 centre (-75, 208) radius 6 clockwise from (-81, 208) to (-80.9351, 208.8804)
  arc A3 centre (-75, 208) radius 6 clockwise from (-69.0649, 208.8804) to (-69, 208)
  arc A4 centre (-75, 208) radius 6 clockwise from (-69, 208) to (-70.2, 204.4)
  circle C1 centre (-75, 212.5) radius 7.5
  point P48 (-75, 212.5)
  point P62 (-75, 212.5)
  point P63 (-82.2709, 214.3397)
  point P64 (-67.7291, 214.3397)
  coincident P48 P62
  coincident C1 P63
  coincident C1 P64
  horizontal L49
  dimension "d331" diameter C1 = 15 (= "WaterFountainHoleFront")
extrude "Extrude3" cut sketch "Sketch4" profile of L9 A2 L47 K4 L48 A3 C1 L49 to an object
sketch "Sketch5" plane through (46.65, 205, -153.85) normal (0, 1, 0) x axis (1, 0, 0)
sketch "Sketch2" plane through (46.65, 205, -153.85) normal (0, 1, 0) x axis (1, 0, 0)
  line L1 (59.05, -154.85) -> (59.05, -78.85)
  line L2 (59.05, -2.85) -> (59.05, -78.85)
  line L3 (72.35, -160.55) -> (62.35, -160.55)
  line L4 (92.35, -160.55) -> (82.35, -160.55)
  line L5 (82.35, -154.85) -> (72.35, -154.85)
  line L6 (102.35, -154.85) -> (92.35, -154.85)
  line L7 (122.35, -154.85) -> (112.35, -154.85)
  line L8 (112.35, -160.55) -> (102.35, -160.55)
  line L9 (132.35, -160.55) -> (122.35, -160.55)
  line L10 (142.35, -154.85) -> (132.35, -154.85)
  line L11 (152.35, -160.55) -> (142.35, -160.55)
  line L12 (154.35, -144.85) -> (154.35, -154.85)
  line L13 (142.35, -154.85) -> (152.35, -154.85)
  line L14 (160.05, -134.85) -> (160.05, -144.85)
  line L15 (160.05, -114.85) -> (160.05, -124.85)
  line L16 (154.35, -124.85) -> (154.35, -134.85)
  line L17 (160.05, -94.85) -> (160.05, -104.85)
  line L18 (154.35, -104.85) -> (154.35, -114.85)
  line L19 (154.35, -84.85) -> (154.35, -94.85)
  line L20 (154.35, -72.85) -> (154.35, -62.85)
  line L21 (160.05, -62.85) -> (160.05, -52.85)
  line L22 (154.35, -32.85) -> (154.35, -42.85)
  line L23 (160.05, -22.85) -> (160.05, -12.85)
  line L24 (154.35, -12.85) -> (154.35, -2.85)
  line L25 (160.05, -2.85) -> (152.35, -2.85)
  line L26 (160.05, 2.85) -> (152.35, 2.85)
  line L27 (160.05, -12.85) -> (160.05, -2.85)
  line L28 (142.35, 2.85) -> (132.35, 2.85)
  line L29 (62.35, -2.85) -> (72.35, -2.85)
  line L30 (72.35, 2.85) -> (62.35, 2.85)
  line L31 (62.35, -2.85) -> (52.35, -2.85)
  line L32 (62.35, 2.85) -> (52.35, 2.85)
  line L33 (52.35, 2.85) -> (160.05, 2.85)
  line L34 (52.35, -160.55) -> (52.35, 2.85)
  line L35 (160.05, -160.55) -> (52.35, -160.55)
  line L36 (160.05, 2.85) -> (160.05, -160.55)
  line L37 (154.35, -2.85) -> (154.35, -154.85)
  line L38 (59.05, -2.85) -> (154.35, -2.85)
  line L39 (59.05, -154.85) -> (59.05, -2.85)
  line L40 (154.35, -154.85) -> (59.05, -154.85)
  line L41 (160.05, -78.85) -> (52.35, -78.85)
  point P54 (160.05, 2.85)
  point P67 (160.05, 2.85)
  point P65 (52.35, 2.85)
  point P68 (52.35, 2.85)
  point P69 (52.35, 2.85)
  point P24 (154.35, -154.85)
  point P72 (154.35, -154.85)
  point P49 (154.35, -2.85)
  point P73 (154.35, -2.85)
  point P74 (154.35, -2.85)
  point P5 (59.05, -2.85)
  point P75 (59.05, -2.85)
  point P76 (59.05, -2.85)
  point P3 (59.05, -154.85)
  point P77 (59.05, -154.85)
  point P78 (59.05, -154.85)
  point P79 (52.35, -78.85)
  point P80 (160.05, -78.85)
  coincident P54 P67
  coincident P65 P68
  coincident P65 P69
  perpendicular L3 L34
  perpendicular L14 L35
  coincident P24 P72
  coincident P49 P73
  coincident P49 P74
  coincident P5 P75
  coincident P5 P76
  coincident P3 P77
  coincident P3 P78
  midpoint L34 P79
  midpoint L36 P80
extrude "Extrude1" new body sketch "Sketch2" profile of L2 L20 L21 L22 L23 L24 L25 L26 L27 L28 L29 L30 L31 L32 L33 L34 L36 L37 L38 L39 L41 no distance stored
sketch "Sketch3" plane through (0, 199.3, 0) normal (0, -1, 0) x axis (1, 0, 0)
  line L1 (206.7, -75) -> (206.7, -156.7)
  line L2 (99, -156.7) -> (99, -75)
  line L3 (206.7, -156.7) -> (99, -156.7)
  line L4 (105.7, 1) -> (105.7, -151)
  line L5 (201, 1) -> (105.7, 1)
  line L6 (201, -151) -> (201, 1)
  line L7 (105.7, -151) -> (201, -151)
  line L8 (99, -156.7) -> (206.7, -156.7)
  line L9 (153.35, -156.7) -> (153.35, -151)
  line L10 (201, -151) -> (153.35, -151)
  line L11 (177.175, -156.7) -> (177.175, -151)
  line L12 (164.675, -151) -> (189.675, -151)
  line L13 (164.675, -156.7) -> (164.675, -151)
  line L14 (189.675, -156.7) -> (164.675, -156.7)
  line L15 (189.675, -151) -> (189.675, -156.7)
  line L16 (164.675, -156.7) -> (189.675, -151)
  line L17 (189.675, -156.7) -> (164.675, -151)
  line L18 (105.7, -151) -> (153.35, -151)
  line L19 (129.525, -157.0018) -> (129.525, -151)
  line L20 (117.025, -156.8509) -> (142.025, -156.8509)
  line L21 (117.025, -151.1509) -> (117.025, -156.8509)
  line L22 (142.025, -151.1509) -> (117.025, -151.1509)
  line L23 (142.025, -156.8509) -> (142.025, -151.1509)
  line L24 (117.025, -151.1509) -> (142.025, -156.8509)
  line L25 (142.025, -151.1509) -> (117.025, -156.8509)
  line L26 (99, -75) -> (206.7, -75)
  line L27 (206.7, -75) -> (201, -75)
  line L28 (201, -62.5) -> (206.7, -62.5)
  line L29 (201, -87.5) -> (201, -62.5)
  line L30 (206.7, -87.5) -> (201, -87.5)
  line L31 (206.7, -62.5) -> (206.7, -87.5)
  line L32 (201, -87.5) -> (206.7, -62.5)
  line L33 (206.7, -87.5) -> (201, -62.5)
  line L34 (201, -87.5) -> (201, -151)
  line L35 (206.7, -119.25) -> (201, -119.25)
  line L36 (201, -106.75) -> (206.7, -106.75)
  line L37 (201, -131.75) -> (201, -106.75)
  line L38 (206.7, -131.75) -> (201, -131.75)
  line L39 (206.7, -106.75) -> (206.7, -131.75)
  line L40 (201, -131.75) -> (206.7, -106.75)
  line L41 (206.7, -131.75) -> (201, -106.75)
  point P16 (153.35, -151)
  point P11 (201, -151)
  point P18 (201, -151)
  point P19 (177.175, -151)
  point P25 (177.175, -153.85)
  point P6 (105.7, -151)
  point P26 (105.7, -151)
  point P27 (129.525, -151)
  point P33 (129.525, -154.0009)
  point P34 (201, -75)
  point P3 (206.7, -75)
  point P35 (206.7, -75)
  point P40 (203.85, -75)
  point P41 (201, -119.25)
  point P42 (206.7, -119.25)
  point P47 (203.85, -119.25)
  point P17 (153.35, -156.7)
  point P20 (177.175, -156.7)
  point P23 (164.675, -156.7)
  point P24 (189.675, -156.7)
  point P22 (164.675, -151)
  point P31 (117.025, -151.1509)
  point P32 (142.025, -151.1509)
  point P30 (117.025, -156.8509)
  point P37 (201, -62.5)
  point P38 (201, -87.5)
  point P39 (206.7, -87.5)
  point P44 (201, -106.75)
  point P45 (201, -131.75)
  point P46 (206.7, -131.75)
  vertical L9
  midpoint L7 P16
  coincident P11 P18
  vertical L11
  midpoint L10 P19
  perpendicular L12 L13
  parallel L12 L14
  parallel L13 L15
  horizontal L12
  coincident L16 P25
  coincident L17 P25
  midpoint L11 P25
  coincident P6 P26
  vertical L19
  midpoint L18 P27
  perpendicular L20 L21
  parallel L20 L22
  parallel L21 L23
  horizontal L20
  coincident L24 P33
  coincident L25 P33
  midpoint L19 P33
  midpoint L6 P34
  coincident P3 P35
  perpendicular L28 L29
  parallel L28 L30
  parallel L29 L31
  horizontal L28
  coincident L32 P40
  coincident L33 P40
  midpoint L27 P40
  midpoint L34 P41
  coincident L1 P42
  perpendicular L1 L35
  perpendicular L36 L37
  parallel L36 L38
  parallel L37 L39
  horizontal L36
  coincident L40 P47
  coincident L41 P47
  midpoint L35 P47
  dimension "d335" distance L7 L8 = 5.7
  dimension "d336" distance P16 P17 = 5.7
  dimension "d338" distance P19 P20 = 5.7
  dimension "d339" distance P23 P24 = 25 (= "WoodConnectionLength")
  dimension "d340" distance P22 P23 = 5.7 (= "WoodThickness")
  dimension "d341" distance P31 P32 = 25 (= "WoodConnectionLength")
  dimension "d342" distance P30 P31 = 5.7 (= "WoodThickness")
  dimension "d343" distance P37 P38 = 25 (= "WoodConnectionLength")
  dimension "d344" distance P38 P39 = 5.7 (= "WoodThickness")
  dimension "d345" distance P44 P45 = 25 (= "WoodConnectionLength")
  dimension "d346" distance P45 P46 = 5.7 (= "WoodThickness")
extrude "Extrude2" cut sketch "Sketch3" profile of L1 L2 L3 L4 L6 L7 L8 L13 L15 L21 L22 L23 L26 L30 L36 L38 to an object
work_plane "WorkPlane2" AlongDistance -81.7
combine "Combine1"
mirror "Mirror2"
sketch "Sketch4" plane through (0, 0, 6.7) normal (0, 0, 1) x axis (1, 0, 0)
  line L1 (100, 139.3) -> (105.7, 139.3)
  line L2 (100, 129.3) -> (100, 139.3)
  line L3 (105.7, 129.3) -> (100, 129.3)
  line L4 (105.7, 119.3) -> (105.7, 129.3)
  line L5 (100, 119.3) -> (105.7, 119.3)
  line L6 (100, 109.3) -> (100, 119.3)
  line L7 (105.7, 109.3) -> (100, 109.3)
  line L8 (105.7, 99.3) -> (105.7, 109.3)
  line L9 (100, 99.3) -> (105.7, 99.3)
  line L10 (100, 85) -> (100, 99.3)
  line L11 (-6.7, 85) -> (100, 85)
  line L12 (-6.7, 75) -> (-6.7, 85)
  line L13 (-1, 75) -> (-6.7, 75)
  line L14 (-1, 65) -> (-1, 75)
  line L15 (-6.7, 65) -> (-1, 65)
  line L16 (-6.7, 55) -> (-6.7, 65)
  line L17 (-1, 55) -> (-6.7, 55)
  line L18 (-1, 45) -> (-1, 55)
  line L19 (-6.7, 45) -> (-1, 45)
  line L20 (-6.7, 35) -> (-6.7, 45)
  line L21 (-1, 35) -> (-6.7, 35)
  line L22 (-1, 25) -> (-1, 35)
  line L23 (-6.7, 25) -> (-1, 25)
  line L24 (-6.7, 15) -> (-6.7, 25)
  line L25 (-1, 15) -> (-6.7, 15)
  line L26 (-1, 5) -> (-1, 15)
  line L27 (-6.7, 5) -> (-1, 5)
  line L28 (-6.7, -5.7) -> (-6.7, 5)
  line L29 (9, -5.7) -> (-6.7, -5.7)
  line L30 (9, 0) -> (9, -5.7)
  line L31 (19, 0) -> (9, 0)
  line L32 (19, -5.7) -> (19, 0)
  line L33 (29, -5.7) -> (19, -5.7)
  line L34 (29, 0) -> (29, -5.7)
  line L35 (39, 0) -> (29, 0)
  line L36 (39, -5.7) -> (39, 0)
  line L37 (49, -5.7) -> (39, -5.7)
  line L38 (49, 0) -> (49, -5.7)
  line L39 (59, 0) -> (49, 0)
  line L40 (59, -5.7) -> (59, 0)
  line L41 (69, -5.7) -> (59, -5.7)
  line L42 (69, 0) -> (69, -5.7)
  line L43 (79, 0) -> (69, 0)
  line L44 (79, -5.7) -> (79, 0)
  line L45 (89, -5.7) -> (79, -5.7)
  line L46 (89, 0) -> (89, -5.7)
  line L47 (99, 0) -> (89, 0)
  line L48 (99, -5.7) -> (99, 0)
  line L49 (109, -5.7) -> (99, -5.7)
  line L50 (109, 0) -> (109, -5.7)
  line L51 (119, 0) -> (109, 0)
  line L52 (119, -5.7) -> (119, 0)
  line L53 (129, -5.7) -> (119, -5.7)
  line L54 (129, 0) -> (129, -5.7)
  line L55 (139, 0) -> (129, 0)
  line L56 (139, -5.7) -> (139, 0)
  line L57 (149, -5.7) -> (139, -5.7)
  line L58 (149, 0) -> (149, -5.7)
  line L59 (159, 0) -> (149, 0)
  line L60 (159, -5.7) -> (159, 0)
  line L61 (169, -5.7) -> (159, -5.7)
  line L62 (169, 0) -> (169, -5.7)
  line L63 (179, 0) -> (169, 0)
  line L64 (179, -5.7) -> (179, 0)
  line L65 (189, -5.7) -> (179, -5.7)
  line L66 (189, 0) -> (189, -5.7)
  line L67 (199, 0) -> (189, 0)
  line L68 (199, -5.7) -> (199, 0)
  line L69 (206.7, -5.7) -> (199, -5.7)
  line L70 (206.7, 10) -> (206.7, -5.7)
  line L71 (201, 10) -> (206.7, 10)
  line L72 (201, 20) -> (201, 10)
  line L73 (206.7, 20) -> (201, 20)
  line L74 (206.7, 30) -> (206.7, 20)
  line L75 (201, 30) -> (206.7, 30)
  line L76 (201, 40) -> (201, 30)
  line L77 (206.7, 40) -> (201, 40)
  line L78 (206.7, 50) -> (206.7, 40)
  line L79 (201, 50) -> (206.7, 50)
  line L80 (201, 60) -> (201, 50)
  line L81 (206.7, 60) -> (201, 60)
  line L82 (206.7, 70) -> (206.7, 60)
  line L83 (201, 70) -> (206.7, 70)
  line L84 (201, 80) -> (201, 70)
  line L85 (206.7, 80) -> (201, 80)
  line L86 (206.7, 90) -> (206.7, 80)
  line L87 (201, 90) -> (206.7, 90)
  line L88 (201, 100) -> (201, 90)
  line L89 (206.7, 100) -> (201, 100)
  line L90 (206.7, 110) -> (206.7, 100)
  line L91 (201, 110) -> (206.7, 110)
  line L92 (201, 120) -> (201, 110)
  line L93 (206.7, 120) -> (201, 120)
  line L94 (206.7, 130) -> (206.7, 120)
  line L95 (201, 130) -> (206.7, 130)
  line L96 (201, 140) -> (201, 130)
  line L97 (206.7, 140) -> (201, 140)
  line L98 (206.7, 150) -> (206.7, 140)
  line L99 (201, 150) -> (206.7, 150)
  line L100 (201, 160) -> (201, 150)
  line L101 (206.7, 160) -> (201, 160)
  line L102 (206.7, 170) -> (206.7, 160)
  line L103 (201, 170) -> (206.7, 170)
  line L104 (201, 180) -> (201, 170)
  line L105 (206.7, 180) -> (201, 180)
  line L106 (206.7, 190) -> (206.7, 180)
  line L107 (201, 190) -> (206.7, 190)
  line L108 (201, 200) -> (201, 190)
  line L109 (206.7, 200) -> (201, 200)
  line L110 (206.7, 210) -> (206.7, 200)
  line L111 (201, 210) -> (206.7, 210)
  line L112 (201, 220) -> (201, 210)
  line L113 (206.7, 220) -> (201, 220)
  line L114 (206.7, 230) -> (206.7, 220)
  line L115 (201, 230) -> (206.7, 230)
  line L116 (201, 245) -> (201, 230)
  line L117 (191, 245) -> (201, 245)
  line L118 (191, 239.3) -> (191, 245)
  line L119 (181, 239.3) -> (191, 239.3)
  line L120 (181, 245) -> (181, 239.3)
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extrude "Extrude8" cut sketch "Sketch4" to an object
